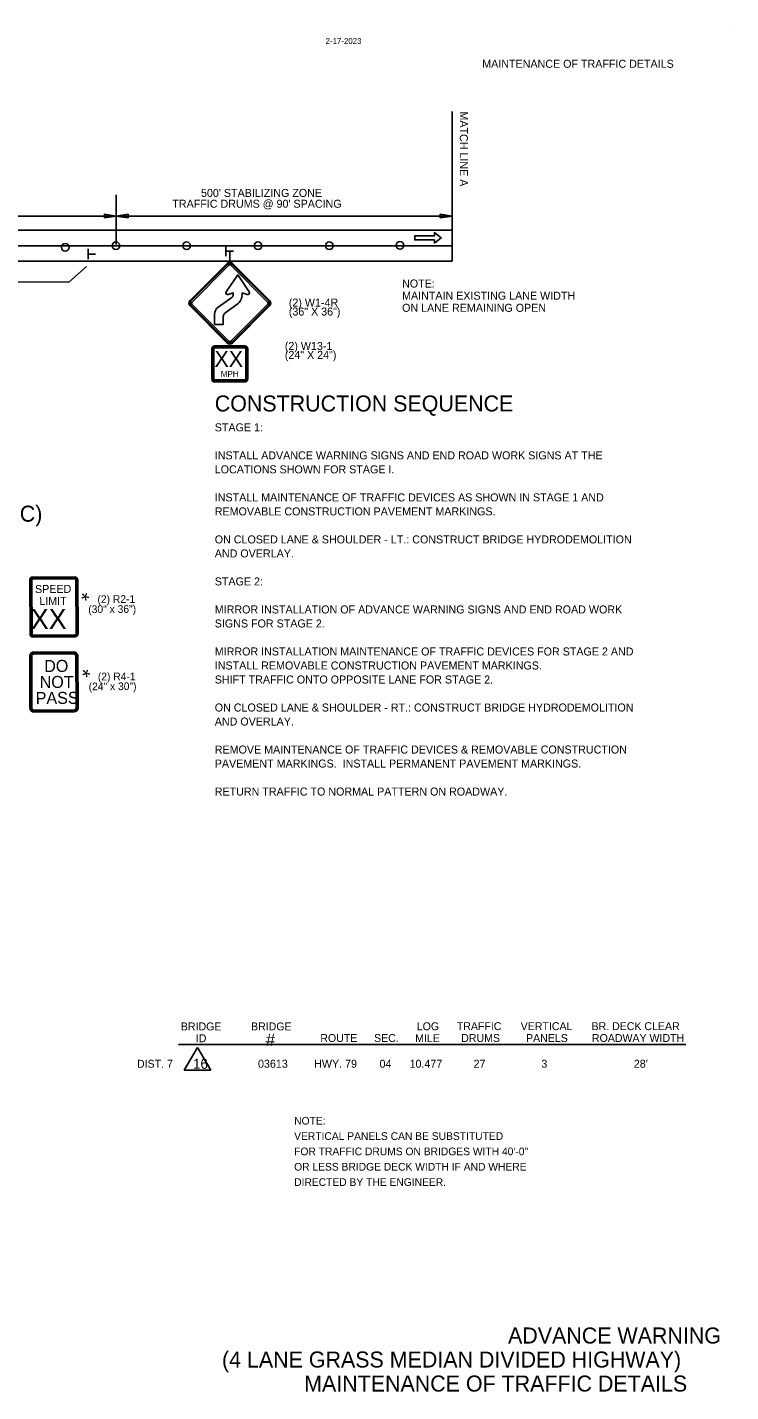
# Model space of a CAD drawing. Extents: x 1930579 to 1938222, y 596452 to 597761.
# Drawn here: x 1937695 to 1938222, y 596536 to 597559 of the extents above; entities that cross this region are included whole.
import ezdxf

# ---------------------------------------------------------------- set-up
doc = ezdxf.new("R2010")
doc.units = 0
for name, color, linetype in [('Default', 7, 'Continuous'), ('P_TC_Signs_Permanent', 7, 'Continuous'), ('R_Border', 7, 'Continuous'), ('R_Border Prem', 7, 'Continuous'), ('R_Striping', 7, 'Continuous')]:
    doc.layers.add(name, color=color, linetype=linetype)

msp = doc.modelspace()

# ---------------------------------------------------------------- linework, layer by layer
at = {"layer": 'Default'}
for p, q in [((1938013.5, 597495.8), (1938013.5, 597383.6)), ((1937761.7, 597433.3), (1937761.7, 597396)), ((1937761.7, 597417.4), (1937394.5, 597417.4)), ((1937752.9, 597416.1), (1937752.9, 597418.8)), ((1937752.9, 597418.8), (1937761.7, 597417.4)), ((1937761.7, 597417.4), (1937752.9, 597416.1)), ((1937761.7, 597417.4), (1937770.6, 597418.8)), ((1938013.5, 597417.4), (1937761.7, 597417.4)), ((1937770.6, 597416.1), (1937761.7, 597417.4)), ((1937770.6, 597418.8), (1937770.6, 597416.1)), ((1938004.6, 597416.1), (1938004.6, 597418.8)), ((1938004.6, 597418.8), (1938013.5, 597417.4)), ((1938013.5, 597417.4), (1938004.6, 597416.1)), ((1938013.5, 597406.7), (1937394.5, 597406.7)), ((1938013.5, 597395.1), (1936726.8, 597395.1)), ((1937844, 597387.2), (1937844, 597395.1)), ((1937740.7, 597385), (1937740.7, 597392.9)), ((1937740.9, 597388.9), (1937746.3, 597388.9)), ((1937844.2, 597391.1), (1937849.6, 597391.1)), ((1938013.5, 597383.6), (1937394.5, 597383.6)), ((1937812.7, 596777.1), (1937822.7, 596794.1)), ((1937822.7, 596794.1), (1937832.7, 596777.1)), ((1937812.7, 596777.1), (1937832.7, 596777.1))]:
    msp.add_line(p, q, dxfattribs=at)
for centre in [(1937723.5, 597393.9), (1937761.5, 597395.1), (1937814.5, 597395.1), (1937868, 597395.1), (1937921.5, 597395.1), (1937974.4, 597395.4)]:
    msp.add_circle(centre, 2.87, dxfattribs=at)
at = {"layer": 'P_TC_Signs_Permanent'}
for p, q in [((1937817.1, 597354.1), (1937844.9, 597381.9)), ((1937817.6, 597353.5), (1937845.4, 597381.4)), ((1937846.2, 597380.6), (1937818.4, 597352.7)), ((1937875.4, 597352.7), (1937847.6, 597380.6)), ((1937848.3, 597381.4), (1937876.2, 597353.5)), ((1937848.9, 597381.9), (1937876.7, 597354.1)), ((1937838.1, 597349), (1937848.3, 597356.3)), ((1937844.9, 597322.2), (1937817.1, 597350.1)), ((1937845.4, 597322.8), (1937817.6, 597350.6)), ((1937818.4, 597351.4), (1937846.2, 597323.6)), ((1937852.2, 597351), (1937843.1, 597344.5)), ((1937847.6, 597323.6), (1937875.4, 597351.4)), ((1937876.2, 597350.6), (1937848.3, 597322.8)), ((1937876.7, 597350.1), (1937848.9, 597322.2)), ((1937833.4, 597317.8), (1937833.4, 597295.3)), ((1937834, 597317.8), (1937834, 597295.3)), ((1937834.9, 597317.8), (1937834.9, 597295.3)), ((1937858.1, 597320.1), (1937835.6, 597320.1)), ((1937858.1, 597319.5), (1937835.6, 597319.5)), ((1937858.1, 597318.6), (1937835.6, 597318.6)), ((1937858.9, 597295.3), (1937858.9, 597317.8)), ((1937859.8, 597295.3), (1937859.8, 597317.8)), ((1937860.4, 597295.3), (1937860.4, 597317.8)), ((1937835.6, 597294.6), (1937858.1, 597294.6)), ((1937835.6, 597293.7), (1937858.1, 597293.7)), ((1937835.6, 597293.1), (1937858.1, 597293.1)), ((1937696.9, 597144.6), (1937697.2, 597104.1)), ((1937697.5, 597144.6), (1937697.7, 597104.1)), ((1937698.4, 597144.6), (1937698.7, 597104.1)), ((1937730.7, 597147), (1937699.2, 597146.8)), ((1937730.7, 597146.4), (1937699.2, 597146.3)), ((1937730.7, 597145.5), (1937699.2, 597145.3)), ((1937731.7, 597104.2), (1937731.4, 597144.7)), ((1937732.6, 597104.3), (1937732.4, 597144.8)), ((1937733.2, 597104.3), (1937732.9, 597144.8)), ((1937699.4, 597103.3), (1937730.9, 597103.5)), ((1937699.4, 597102.4), (1937730.9, 597102.6)), ((1937699.4, 597101.8), (1937730.9, 597102)), ((1937729.9, 597090.7), (1937699.9, 597090.6)), ((1937729.9, 597090.1), (1937699.9, 597090)), ((1937729.9, 597089.2), (1937699.9, 597089.1)), ((1937696.9, 597087.6), (1937697.1, 597048.6)), ((1937697.5, 597087.6), (1937697.7, 597048.6)), ((1937698.4, 597087.6), (1937698.6, 597048.6)), ((1937731.6, 597048.8), (1937731.4, 597087.8)), ((1937732.5, 597048.8), (1937732.3, 597087.8)), ((1937733.1, 597048.8), (1937732.9, 597087.8)), ((1937700.2, 597047.1), (1937730.2, 597047.2)), ((1937700.2, 597046.2), (1937730.2, 597046.3)), ((1937700.2, 597045.6), (1937730.2, 597045.7))]:
    msp.add_line(p, q, dxfattribs=at)
for points in [[(1937844.2, 597360.6), (1937852.8, 597373.2), (1937861.4, 597360.6)], [(1937849.5, 597358.6), (1937849.5, 597359.8), (1937845.7, 597358.6)], [(1937859.9, 597358.6), (1937856.1, 597359.8), (1937856.1, 597358.6)], [(1937842, 597342.2), (1937842, 597336.1), (1937835.4, 597336.1), (1937835.4, 597343.7)]]:
    msp.add_lwpolyline(points, dxfattribs=at)
for centre, radius, start, end in [((1937846.9, 597379.9), 2.81, 45, 135), ((1937846.9, 597379.9), 2.06, 45, 135), ((1937846.9, 597379.9), 0.937, 45, 135), ((1937819, 597352.1), 2.81, 135, 225), ((1937845.3, 597359.8), 1.31, 145.6763, 287.8128), ((1937846.7, 597358.6), 2.81, 305.7733, 0), ((1937846.7, 597358.6), 9.37, 305.7733, 0), ((1937860.3, 597359.8), 1.31, 252.1872, 34.3237), ((1937874.7, 597352.1), 2.81, 315, 45), ((1937819, 597352.1), 2.06, 135, 225), ((1937819, 597352.1), 0.937, 135, 225), ((1937842, 597343.7), 6.56, 125.7733, 180), ((1937844.8, 597342.2), 2.81, 125.7733, 180), ((1937874.7, 597352.1), 0.937, 315, 45), ((1937874.7, 597352.1), 2.06, 315, 45), ((1937846.9, 597324.2), 0.937, 225, 315), ((1937835.6, 597317.8), 2.25, 90, 180), ((1937835.6, 597317.8), 1.69, 90, 180), ((1937835.6, 597317.8), 0.75, 90, 180), ((1937846.9, 597324.2), 2.81, 225, 315), ((1937846.9, 597324.2), 2.06, 225, 315), ((1937858.1, 597317.8), 2.25, 360, 90), ((1937858.1, 597317.8), 1.69, 360, 90), ((1937858.1, 597317.8), 0.75, 360, 90), ((1937835.6, 597295.3), 2.25, 180, 270), ((1937835.6, 597295.3), 1.69, 180, 270), ((1937835.6, 597295.3), 0.75, 180, 270), ((1937858.1, 597295.3), 2.25, 270, 360), ((1937858.1, 597295.3), 1.69, 270, 360), ((1937858.1, 597295.3), 0.75, 270, 360), ((1937699.2, 597144.6), 2.25, 90.312, 180.312), ((1937699.2, 597144.6), 1.69, 90.312, 180.312), ((1937699.2, 597144.6), 0.75, 90.312, 180.312), ((1937730.7, 597144.7), 2.25, 0.312, 90.312), ((1937730.7, 597144.7), 1.69, 0.312, 90.312), ((1937730.7, 597144.7), 0.75, 0.312, 90.312), ((1937699.4, 597104.1), 2.25, 180.312, 270.312), ((1937699.4, 597104.1), 1.69, 180.312, 270.312), ((1937699.4, 597104.1), 0.75, 180.312, 270.312), ((1937730.9, 597104.2), 2.25, 270.312, 0.312), ((1937730.9, 597104.2), 1.69, 270.312, 0.312), ((1937730.9, 597104.2), 0.75, 270.312, 0.312), ((1937699.9, 597087.6), 3, 90.312, 180.312), ((1937699.9, 597087.6), 2.4, 90.312, 180.312), ((1937699.9, 597087.6), 1.5, 90.312, 180.312), ((1937729.9, 597087.7), 3, 0.312, 90.312), ((1937729.9, 597087.7), 2.4, 0.312, 90.312), ((1937729.9, 597087.7), 1.5, 0.312, 90.312), ((1937700.1, 597048.6), 3, 180.312, 270.312), ((1937700.1, 597048.6), 2.4, 180.312, 270.312), ((1937700.1, 597048.6), 1.5, 180.312, 270.312), ((1937730.1, 597048.7), 3, 270.312, 0.312), ((1937730.1, 597048.7), 2.4, 270.312, 0.312), ((1937730.1, 597048.7), 1.5, 270.312, 0.312)]:
    msp.add_arc(centre, radius, start, end, dxfattribs=at)
at = {"layer": 'R_Border'}
for p, q in [((1937846.9, 597391.1), (1937846.9, 597382.7)), ((1937808.3, 596796.3), (1938188.7, 596796.3))]:
    msp.add_line(p, q, dxfattribs=at)
msp.add_lwpolyline([(1937518.5, 597376), (1937530.3, 597369.1), (1937609.5, 597369.1), (1937610.2, 597360.7), (1937613, 597368.4), (1937726.2, 597367.7), (1937739.4, 597379.5)], dxfattribs=at)
at = {"layer": 'R_Border Prem'}
msp.add_line((1938222.3, 597558.9), (1938222.3, 597558.9), dxfattribs=at)
at = {"layer": 'R_Striping'}
msp.add_lwpolyline([(1938000.2, 597397), (1938005.4, 597401), (1938000.2, 597405), (1938000.2, 597402.5), (1937985.5, 597402.5), (1937985.5, 597399.5), (1938000.2, 597399.5)], close=True, dxfattribs=at)

# ---------------------------------------------------------------- texts
at = {"layer": 'Default'}
for s, height, rotation, p in [('MATCH LINE A', 6, 270, (1938019.3, 597495.8)), ("500' STABILIZING ZONE", 6, 360, (1937825.3, 597431.7)), ("TRAFFIC DRUMS @ 90' SPACING ", 6, 360, (1937803.8, 597423.6)), ('(IN DIRECTION OF TRAFFIC)', 12, 360, (1937488, 597188.3))]:
    msp.add_text(s, height=height, rotation=rotation, dxfattribs=at).set_placement(p)
for s, height, p in [('16', 7.5, (1937819.3, 596778.2)), ('03613', 6, (1937868, 596779)), ('HWY. 79', 6, (1937910.1, 596779)), ('04', 6, (1937959.1, 596779)), ('10.477', 6, (1937981.6, 596779)), ('27', 6, (1938029.6, 596779)), ('3', 6, (1938080.4, 596779)), ("28'", 6, (1938149.7, 596779))]:
    msp.add_text(s, height=height, dxfattribs=at).set_placement(p)
at = {"layer": 'P_TC_Signs_Permanent'}
for s, height, rotation, p in [('XX', 12, 360, (1937835.4, 597304.3)), ('MPH', 4.5, 360, (1937840.1, 597296.8)), ('SPEED', 6, 0.312, (1937700.9, 597134.8)), ('LIMIT', 6, 0.312, (1937704.1, 597125.8)), ('XX', 15, 0.312, (1937697.8, 597107.8)), ('DO', 9, 0.312, (1937707.8, 597075.6)), ('NOT', 9, 0.2716, (1937704.4, 597063.6)), ('PASS', 9, 0.312, (1937701.4, 597051.6))]:
    msp.add_text(s, height=height, rotation=rotation, dxfattribs=at).set_placement(p)
at = {"layer": 'R_Border'}
for s, height, rotation, p in [('NOTE:', 6, 360, (1937976, 597363.8)), ('(2) W1-4R', 6, 360, (1937891.1, 597349.5)), ('MAINTAIN EXISTING LANE WIDTH ', 6, 360, (1937976, 597354.7)), ('(36" X 36")', 6, 360, (1937891.1, 597342.8)), ('ON LANE REMAINING OPEN', 6, 360, (1937976, 597345.6)), ('(2) W13-1', 6, 360, (1937888.1, 597317)), ('(24" X 24")', 6, 360, (1937888.1, 597310.3)), ('CONSTRUCTION SEQUENCE', 12, 360, (1937835.6, 597270.9)), ('STAGE 1:', 6, 360, (1937835.6, 597256)), ('INSTALL ADVANCE WARNING SIGNS AND END ROAD WORK SIGNS AT THE', 6, 360, (1937835.6, 597235)), ('LOCATIONS SHOWN FOR STAGE I.  ', 6, 360, (1937835.6, 597224.5)), ('INSTALL MAINTENANCE OF TRAFFIC DEVICES AS SHOWN IN STAGE 1 AND', 6, 360, (1937835.6, 597203.5)), ('REMOVABLE CONSTRUCTION PAVEMENT MARKINGS.', 6, 360, (1937835.6, 597193)), ('ON CLOSED LANE & SHOULDER - LT.: CONSTRUCT BRIDGE HYDRODEMOLITION ', 6, 360, (1937835.6, 597172)), ('AND OVERLAY.', 6, 360, (1937835.6, 597161.5)), ('STAGE 2:', 6, 360, (1937835.6, 597140.5)), ('*', 11.5, 45, (1937742.3, 597124)), ('(2) R2-1', 5.76, 0.312, (1937747.7, 597127.3)), ('(30" x 36")', 5.76, 0.312, (1937740.8, 597119.8)), ('MIRROR INSTALLATION OF ADVANCE WARNING SIGNS AND END ROAD WORK', 6, 360, (1937835.6, 597119.5)), ('SIGNS FOR STAGE 2.  ', 6, 360, (1937835.6, 597109)), ('MIRROR INSTALLATION MAINTENANCE OF TRAFFIC DEVICES FOR STAGE 2 AND', 6, 360, (1937835.6, 597088)), ('INSTALL REMOVABLE CONSTRUCTION PAVEMENT MARKINGS.', 6, 360, (1937835.6, 597077.5)), ('*', 11.5, 45, (1937743, 597066.6)), ('(24" x 30")', 5.76, 0.312, (1937741.1, 597061.9)), ('(2) R4-1', 5.76, 0.312, (1937748, 597069.3)), ('SHIFT TRAFFIC ONTO OPPOSITE LANE FOR STAGE 2.', 6, 360, (1937835.6, 597067)), ('ON CLOSED LANE & SHOULDER - RT.: CONSTRUCT BRIDGE HYDRODEMOLITION', 6, 360, (1937835.6, 597046)), ('AND OVERLAY.', 6, 360, (1937835.6, 597035.5)), ('REMOVE MAINTENANCE OF TRAFFIC DEVICES & REMOVABLE CONSTRUCTION', 6, 360, (1937835.6, 597014.5)), ('PAVEMENT MARKINGS.  INSTALL PERMANENT PAVEMENT MARKINGS.', 6, 360, (1937835.6, 597004)), ('RETURN TRAFFIC TO NORMAL PATTERN ON ROADWAY. ', 6, 360, (1937835.6, 596983)), ('BRIDGE ', 5.93, 360, (1937810.2, 596807)), ('BRIDGE ', 5.93, 360, (1937862.8, 596807)), ('LOG', 5.93, 360, (1937987, 596807.1)), ('TRAFFIC     ', 5.929, 360, (1938017, 596807.2)), ('VERTICAL', 5.93, 360, (1938064.9, 596807.2)), ('BR. DECK CLEAR', 5.929, 360, (1938118, 596807.2)), ('ID', 5.93, 360, (1937821.4, 596798.1)), ('#', 9.5, 360, (1937873.8, 596795.2)), ('ROUTE', 5.93, 360, (1937914.7, 596798.3)), ('SEC.', 5.93, 360, (1937955, 596798.3)), ('MILE', 5.93, 360, (1937985.8, 596798.2)), ('DRUMS', 5.93, 360, (1938020.3, 596798.3)), ('PANELS', 5.93, 360, (1938068.9, 596798.3)), ('ROADWAY WIDTH', 5.929, 360, (1938118.3, 596798.3)), ('DIST. 7', 5.93, 360, (1937777.3, 596779)), ('NOTE: ', 5.76, 360, (1937895.1, 596736.4)), ('VERTICAL PANELS CAN BE SUBSTITUTED ', 5.76, 360, (1937895.1, 596724.9)), ('FOR TRAFFIC DRUMS ON BRIDGES WITH 40\'-0"', 5.76, 360, (1937895.1, 596713.4)), ('OR LESS BRIDGE DECK WIDTH IF AND WHERE ', 5.76, 360, (1937895.1, 596701.9)), ('DIRECTED BY THE ENGINEER.', 5.76, 360, (1937895.1, 596690.4)), ('ADVANCE WARNING ', 12, 360, (1938055.4, 596572.3)), ('(4 LANE GRASS MEDIAN DIVIDED HIGHWAY) ', 12, 360, (1937841, 596554.3)), ('MAINTENANCE OF TRAFFIC DETAILS ', 12, 360, (1937902.6, 596536.3))]:
    msp.add_text(s, height=height, rotation=rotation, dxfattribs=at).set_placement(p)
at = {"layer": 'R_Border Prem'}
msp.add_text('2-17-2023', height=4.4, dxfattribs=at).set_placement((1937918.7, 597546.4))
msp.add_text('MAINTENANCE OF TRAFFIC DETAILS', height=6, rotation=360, dxfattribs=at).set_placement((1938036.1, 597528.5))

doc.saveas('drawing.dxf')
